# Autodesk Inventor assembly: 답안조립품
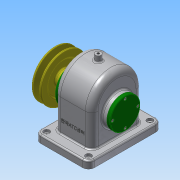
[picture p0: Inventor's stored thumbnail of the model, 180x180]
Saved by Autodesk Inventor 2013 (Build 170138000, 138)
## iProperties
Created: 2016-10
Part Number: 답안조립품
Document SubType Name: Assembly
Designer: Administrator
Author: Administrator
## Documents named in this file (14)
- C:\Users\Administrator\Desktop\461008V1022\답안조립품.iam
- C:\Users\Administrator\Desktop\461008V1022\본체.ipt
- C:\Users\Administrator\Desktop\461008V1022\앞커버.ipt
- C:\Users\Administrator\Desktop\461008V1022\뒤커버.ipt
- C:\Users\Administrator\Desktop\461008V1022\볼트 M3 x 8.ipt
- C:\Users\Administrator\Desktop\461008V1022\오일씰 28 40 8.ipt
- C:\Users\Administrator\Desktop\461008V1022\베어링 6203.ipt
- C:\Users\Administrator\Desktop\461008V1022\축.ipt
- C:\Users\Administrator\Desktop\461008V1022\키 - 6 x 6 x 22.ipt
- C:\Users\Administrator\Desktop\461008V1022\스퍼기어.ipt
- C:\Users\Administrator\Desktop\461008V1022\키 - 5 x 5 x 18.ipt
- C:\Users\Administrator\Desktop\461008V1022\V-벨트풀리.ipt
- C:\Users\Administrator\Desktop\461008V1022\멈춤나사 - M4x10.ipt
- C:\Users\Administrator\Desktop\461008V1022\부시.ipt
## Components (9 placed, 2 different names)
1. V-벨트풀리:1 — 각도:4
2. ISO 4762 M3 x 8:1
3. ISO 4762 M3 x 8:3
4. ISO 4762 M3 x 8:4
5. ISO 4762 M3 x 8:5
6. ISO 4762 M3 x 8:2
7. ISO 4762 M3 x 8:6
8. ISO 4762 M3 x 8:7
9. ISO 4762 M3 x 8:8
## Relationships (1: Angle 1)
- 각도:4 [Angle]: V-벨트풀리:1
